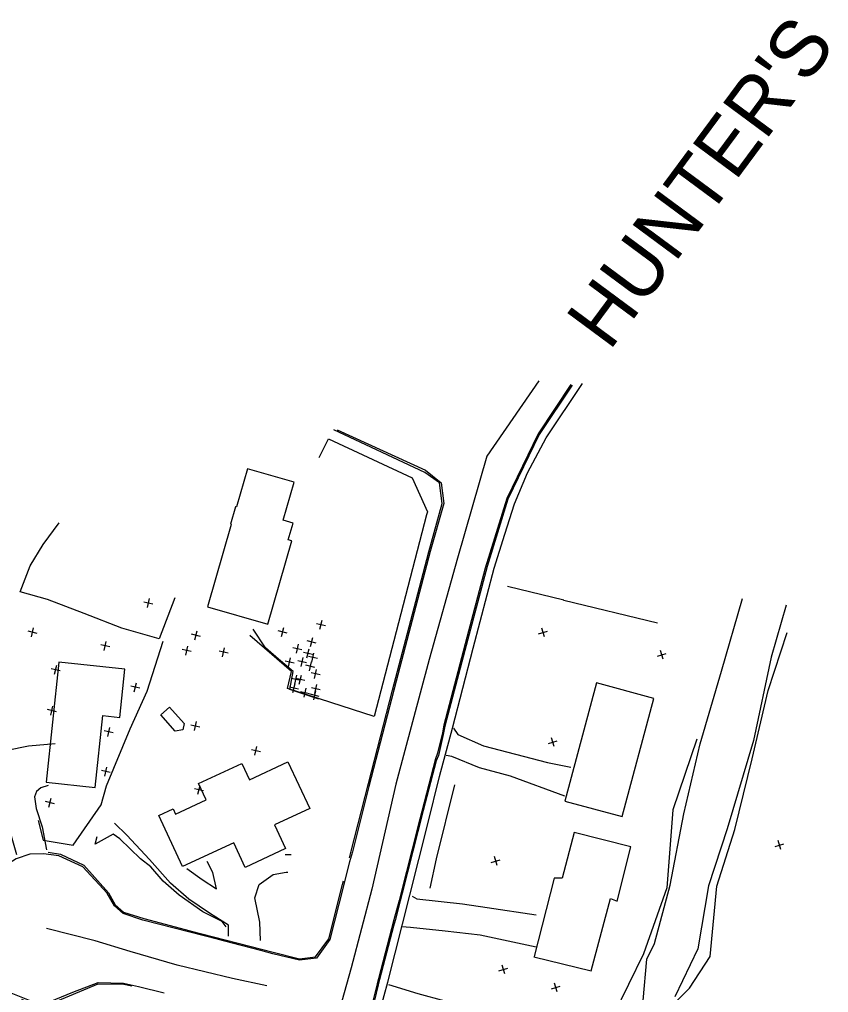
# Model space of a CAD drawing. Extents: x 4711259 to 4716401, y 890074 to 892728.
# Drawn here: x 4713887 to 4714325, y 892014 to 892542 of the extents above; entities that cross this region are included whole.
import ezdxf

# ---------------------------------------------------------------- set-up
doc = ezdxf.new("R2010")
doc.units = 0
for name, color, linetype in [('E_HY_STORM_Ditch', 7, 'Continuous'), ('E_RDWY_PHOTOG_Eave', 7, 'Continuous'), ('E_RDWY_PHOTOG_Fence', 7, 'Continuous'), ('E_RDWY_ROAD_Approach', 7, 'Continuous'), ('E_RDWY_ROAD_Curb', 7, 'Continuous'), ('E_RDWY_ROAD_Fence', 7, 'Continuous'), ('E_RDWY_ROAD_NameTx', 7, 'Continuous'), ('E_RDWY_ROAD_Sidewalk', 7, 'Continuous'), ('E_RDWY_ROAD_TBofCurb', 7, 'Continuous'), ('E_TERR_DTM_BrkLines', 7, 'Continuous'), ('E_TERR_DTM_RandomPt', 7, 'Continuous')]:
    doc.layers.add(name, color=color, linetype=linetype)

msp = doc.modelspace()

# ---------------------------------------------------------------- linework, layer by layer
at = {"layer": 'E_HY_STORM_Ditch'}
for points in [[(4714224.77, 892009.61), (4714226.65, 892032.11), (4714230.83, 892040.51), (4714239.33, 892072.28), (4714246.81, 892110.99), (4714255.61, 892148.9), (4714267.28, 892188.36), (4714278.6, 892227.78)], [(4714302.3, 892224.08), (4714294.17, 892195.83), (4714284.66, 892150.64), (4714270.27, 892102.78), (4714260.1, 892071.81), (4714254.33, 892037.64), (4714241.88, 892011.7)]]:
    msp.add_lwpolyline(points, dxfattribs=at)
at = {"layer": 'E_RDWY_PHOTOG_Eave'}
for points in [[(4714021.22, 892213.8), (4714034.23, 892258.99), (4714032.31, 892259.54), (4714034.91, 892268.56), (4714029.45, 892270.13), (4714035.4, 892290.81), (4714010.19, 892298.06), (4714004.23, 892277.36), (4714003.65, 892277.52), (4714000.92, 892268.02), (4714001.28, 892267.91), (4713988.42, 892223.24)], [(4713927.55, 892125.22), (4713931.66, 892164.16), (4713940.85, 892163.19), (4713943.63, 892189.44), (4713907.94, 892193.21), (4713901.06, 892128.02)], [(4714199.5, 892181.91), (4714182.23, 892117.81), (4714213.33, 892109.43), (4714230.6, 892173.53)], [(4713967.88, 892168.81), (4713975.87, 892159.82), (4713975.11, 892156.42), (4713970.95, 892155.7), (4713963.08, 892164.55)], [(4713983.65, 892127.35), (4714007.07, 892138.26), (4714011.2, 892129.4), (4714032.13, 892139.15), (4714043.94, 892113.78), (4714024.77, 892104.85), (4714030.75, 892092.02), (4714008.95, 892081.87), (4714002.71, 892095.25), (4713974.92, 892082.31), (4713962.03, 892109.99), (4713969.81, 892113.61), (4713971.12, 892110.78), (4713987.75, 892118.53)]]:
    msp.add_lwpolyline(points, close=True, dxfattribs=at)
msp.add_lwpolyline([(4714165.49, 892033.38), (4714196.59, 892025.71), (4714206.95, 892065.06), (4714210.63, 892063.51), (4714218.14, 892092.92), (4714187.26, 892100.83), (4714180.83, 892076), (4714176.44, 892075.94), (4714165.58, 892033.54), (4714165.58, 892033.54)], dxfattribs=at)
at = {"layer": 'E_RDWY_PHOTOG_Fence'}
for points in [[(4714049.02, 892304.21), (4714054.1, 892314.4), (4714099.51, 892293.18), (4714107.77, 892274.68), (4714107.22, 892273.19), (4714090.84, 892209.63), (4714078.92, 892163.65), (4714031.93, 892178.96), (4714034.01, 892188.12), (4714011.51, 892207.65)], [(4714232.46, 892214.26), (4714181.72, 892226.68), (4714181.72, 892226.8), (4714151.09, 892234.28)], [(4713896.64, 892107.28), (4713899.42, 892096.55), (4713915.64, 892093.89), (4713930.79, 892115.78), (4713933.71, 892126.18), (4713946.59, 892156.96), (4713955.76, 892177.52), (4713964.49, 892204.56)]]:
    msp.add_lwpolyline(points, dxfattribs=at)
at = {"layer": 'E_RDWY_ROAD_Approach'}
for points in [[(4714121.86, 892157.45), (4714124.31, 892153.96), (4714138.2, 892147.72), (4714172.95, 892138.83), (4714185.43, 892136.29)], [(4713885.12, 892088.7), (4713881.53, 892101.38), (4713879.59, 892113.76), (4713872.89, 892119.45), (4713866.06, 892130.02), (4713866.28, 892138.39), (4713879.91, 892145.37), (4713891.41, 892147.84), (4713905.89, 892149.14)], [(4714182.26, 892120.45), (4714152.85, 892131.25), (4714135.92, 892135.87), (4714120.97, 892142.03), (4714117.99, 892142.53)], [(4713902.04, 892126.24), (4713898.08, 892125.03), (4713895.79, 892122.95), (4713894.59, 892120.11), (4713895.56, 892113.87), (4713898.9, 892103.94), (4713901.11, 892091.29)], [(4713999.92, 892044.49), (4713999.95, 892050.45), (4713989.61, 892057.05), (4713978.32, 892064.64), (4713968.49, 892073.21), (4713956.95, 892086.18), (4713944.73, 892099.29), (4713938.01, 892105.93)], [(4714033.9, 892088.7), (4714030.63, 892088.64)], [(4713977.24, 892081.28), (4713985.56, 892075.29), (4713993.34, 892070.17), (4713991.37, 892079.03), (4713988.23, 892085.08)], [(4714017.29, 892042.2), (4714016.83, 892052.05), (4714014.1, 892065.33), (4714016.58, 892072.62), (4714024.02, 892078.07), (4714031.16, 892079.24), (4714032.13, 892079.2)], [(4714099.42, 892066.31), (4714101.94, 892064.71), (4714126.77, 892062.03), (4714140.23, 892060.08), (4714166.8, 892056.2)], [(4714166.69, 892038.64), (4714136.36, 892045.02), (4714117.37, 892047.18), (4714098.53, 892049.17), (4714093.91, 892049.62)], [(4714086.66, 892018.41), (4714102.6, 892013.4), (4714131.87, 892005.49), (4714133.24, 892005.31), (4714129.98, 891991.54), (4714101.4, 891997.44), (4714081.87, 891999.61)]]:
    msp.add_lwpolyline(points, dxfattribs=at)
at = {"layer": 'E_RDWY_ROAD_Curb'}
for points in [[(4714185.59, 892343.87), (4714167.83, 892317.05), (4714150.75, 892281.89), (4714139.14, 892244.17), (4714129.12, 892206.5), (4714116.62, 892158.93), (4714115.84, 892154.79), (4714113.27, 892143.75), (4714112.11, 892140.68), (4714102.32, 892103.11), (4714093.52, 892068.32), (4714092.5, 892063.96), (4714089.62, 892053.49), (4714081.27, 892021.32), (4714080.55, 892018.71), (4714076.89, 892004.21)], [(4714058.84, 892319.23), (4714106.63, 892297.27), (4714115.14, 892290.55), (4714116.56, 892279.31), (4714109.3, 892253.16), (4714090.75, 892182.91), (4714075.98, 892125.67), (4714067.07, 892090.34), (4714065.54, 892084.79), (4714063.16, 892075.73), (4714062.25, 892071.91), (4714054.78, 892042.65), (4714047.64, 892032.69), (4714038.41, 892031.48), (4714023.91, 892034.98)], [(4714023.91, 892034.98), (4714017.42, 892036.71), (4714001.97, 892040.77), (4713994.49, 892042.66), (4713970.45, 892048.83), (4713953.32, 892053.28), (4713942.78, 892056.81), (4713938.03, 892060.92), (4713934.02, 892067.79), (4713920.81, 892082.1), (4713907.85, 892088.19), (4713899.49, 892089.29), (4713892.15, 892089.02), (4713884.8, 892086.46), (4713875.68, 892080.9), (4713868.1, 892073.81), (4713864.21, 892068.13), (4713861.6, 892061.34), (4713859.71, 892049.58), (4713860.7, 892038.1), (4713863.41, 892029.26), (4713873.16, 892019.33), (4713880.92, 892014.1), (4713891.71, 892009.84)], [(4713903.21, 892009.01), (4713915.39, 892014.11), (4713929.19, 892019.4), (4713942.9, 892019.01), (4713951.12, 892017.28), (4713964.96, 892013.71)]]:
    msp.add_lwpolyline(points, dxfattribs=at)
at = {"layer": 'E_RDWY_ROAD_Fence'}
for points in [[(4713970.77, 892228), (4713962.2, 892205.88), (4713941.99, 892211.56), (4713921.61, 892219.56), (4713901.71, 892227.16), (4713886.89, 892231.39), (4713892.27, 892245.38), (4713899.35, 892257.06), (4713908.06, 892268.73)], [(4714048.93, 892173.03), (4714033.09, 892178.31), (4714034.99, 892188.09), (4714027.02, 892194.74), (4714019.95, 892200.9), (4714013.23, 892211.06)]]:
    msp.add_lwpolyline(points, dxfattribs=at)
at = {"layer": 'E_RDWY_ROAD_Sidewalk'}
msp.add_lwpolyline([(4714078.41, 891990.71), (4714086.26, 892019.55), (4714098.18, 892066.73), (4714107.89, 892105.42), (4714114.38, 892131.2), (4714121.37, 892157.46), (4714132.5, 892200.86), (4714143.98, 892244.16), (4714149.64, 892262.62), (4714154.94, 892279.03), (4714162.04, 892295.84), (4714172.13, 892314.87), (4714191.76, 892344.31)], dxfattribs=at)
at = {"layer": 'E_RDWY_ROAD_TBofCurb'}
for points in [[(4714186.17, 892343.39), (4714168.35, 892316.66), (4714151.38, 892281.65), (4714140.16, 892245.03), (4714129.58, 892205.72), (4714117.22, 892158.51), (4714116.25, 892153.93), (4714113.8, 892142.54), (4714112.46, 892139.63), (4714105.45, 892112.78), (4714094.05, 892067.92), (4714093, 892063.74), (4714090.17, 892053), (4714089.41, 892049.92), (4714081.83, 892020.96), (4714081.11, 892018.16), (4714077.58, 892003.88)], [(4714065.54, 892087.02), (4714066.47, 892090.69), (4714075.82, 892127.4), (4714088.75, 892177.97), (4714101.44, 892226.15), (4714108.59, 892252.98), (4714115.77, 892279.24), (4714114.23, 892290.4), (4714106.41, 892296.14), (4714057.03, 892319.27)], [(4713902.02, 892090.18), (4713908.68, 892089.08), (4713921.43, 892083), (4713934.72, 892068.11), (4713938.44, 892061.58), (4713942.9, 892057.63), (4713953.93, 892054.05), (4713979.08, 892047.5), (4714024.08, 892035.88)], [(4714024.08, 892035.88), (4714038.36, 892032.23), (4714047.13, 892033.35), (4714054.24, 892043.09), (4714061.78, 892072.48), (4714062.24, 892074.52)], [(4713947.37, 892017.37), (4713943.1, 892018.25), (4713929.03, 892018.49), (4713903.59, 892007.88), (4713890.93, 892008.91), (4713887.83, 892010.1)]]:
    msp.add_lwpolyline(points, dxfattribs=at)
at = {"layer": 'E_TERR_DTM_BrkLines'}
for points in [[(4714168.21, 892345.87), (4714139.93, 892304.85), (4714123.98, 892249.61), (4714108.73, 892194.68), (4714090.62, 892126.91), (4714077.61, 892070.09), (4714066.36, 892027.31), (4714051.14, 891973.2), (4714037.46, 891917.08), (4714024.07, 891859.57), (4714022.9, 891844.03), (4714023.74, 891795.26), (4714028.59, 891737.22), (4714034.45, 891684.14), (4714037.34, 891645.06), (4714038.63, 891626.49), (4714035.43, 891578.63), (4714032.35, 891531.62), (4714024.41, 891465.89), (4714020.79, 891430.37), (4714019.31, 891383.24)], [(4714226.91, 891993.34), (4714249.79, 892016.32), (4714261.05, 892033.57), (4714264.69, 892071.58), (4714274.41, 892102.38), (4714283.88, 892140.78), (4714292.61, 892177.74), (4714302.89, 892209.33)], [(4714253.82, 892151.5), (4714240.84, 892113.08), (4714237.67, 892070.75), (4714224.89, 892034.98), (4714208.58, 892001.73)], [(4714109.29, 892070.67), (4714112.58, 892086.51), (4714122.58, 892126.63)], [(4713998.56, 892049.67), (4713996.5, 892052.5), (4713986, 892057.8), (4713973.06, 892066.86), (4713964.45, 892074.36), (4713957.73, 892082.16), (4713952.08, 892086.42), (4713940.86, 892097.33), (4713937.32, 892099.91), (4713927.53, 892094.52), (4713928.6, 892098.56)], [(4714020.67, 892017.52), (4714002.03, 892021.5), (4713972.09, 892028.76), (4713946.45, 892036.15), (4713927.53, 892042.04), (4713901.1, 892048.63)]]:
    msp.add_lwpolyline(points, dxfattribs=at)
at = {"layer": 'E_TERR_DTM_RandomPt'}
for p, q in [((4713958.91, 892224.68), (4713954.04, 892225.82)), ((4713955.91, 892222.82), (4713957.05, 892227.68)), ((4714052.47, 892212.9), (4714047.6, 892214.04)), ((4714049.46, 892211.03), (4714050.6, 892215.9)), ((4713896.03, 892208.78), (4713891.16, 892209.92)), ((4713893.02, 892206.92), (4713894.16, 892211.79)), ((4713984.66, 892207.18), (4713979.79, 892208.32)), ((4713981.65, 892205.32), (4713982.79, 892210.19)), ((4714031.66, 892208.96), (4714026.79, 892210.1)), ((4714028.65, 892207.1), (4714029.8, 892211.97)), ((4714168.05, 892208.57), (4714172.84, 892210.02)), ((4714171.17, 892206.9), (4714169.72, 892211.69)), ((4713935.47, 892201.46), (4713930.6, 892202.6)), ((4713932.46, 892199.6), (4713933.61, 892204.47)), ((4713976.65, 892197.07), (4713977.8, 892201.93)), ((4714036.68, 892198.02), (4714037.82, 892202.89)), ((4714047.39, 892203.56), (4714042.53, 892204.71)), ((4714044.39, 892201.7), (4714045.53, 892206.57)), ((4713979.66, 892198.93), (4713974.79, 892200.07)), ((4713999.6, 892198.02), (4713994.73, 892199.17)), ((4713996.59, 892196.16), (4713997.74, 892201.03)), ((4714039.69, 892199.88), (4714034.82, 892201.03)), ((4714045.39, 892197.36), (4714040.53, 892198.51)), ((4714042.39, 892195.5), (4714043.53, 892200.37)), ((4714045.06, 892193.26), (4714046.21, 892198.13)), ((4714232.49, 892196.39), (4714237.28, 892197.83)), ((4714235.61, 892194.72), (4714234.16, 892199.5)), ((4713905.55, 892186.61), (4713906.69, 892191.48)), ((4714035.44, 892192.59), (4714030.57, 892193.73)), ((4714032.44, 892190.73), (4714033.58, 892195.6)), ((4714042.25, 892192.74), (4714037.38, 892193.88)), ((4714039.24, 892190.87), (4714040.39, 892195.74)), ((4714046.74, 892190.35), (4714041.87, 892191.49)), ((4714048.07, 892195.12), (4714043.2, 892196.27)), ((4714043.73, 892188.49), (4714044.88, 892193.35)), ((4713908.55, 892188.48), (4713903.69, 892189.62)), ((4714035.85, 892181.33), (4714036.99, 892186.19)), ((4714038.26, 892181.29), (4714039.4, 892186.16)), ((4714049.54, 892186.26), (4714044.68, 892187.41)), ((4714046.54, 892184.4), (4714047.68, 892189.27)), ((4713948.77, 892177.14), (4713949.91, 892182.01)), ((4714038.85, 892183.19), (4714033.98, 892184.33)), ((4714034.81, 892176.71), (4714035.96, 892181.58)), ((4714041.27, 892183.16), (4714036.4, 892184.3)), ((4714046.65, 892176.23), (4714047.8, 892181.1)), ((4713951.78, 892179), (4713946.91, 892180.15)), ((4714037.82, 892178.57), (4714032.95, 892179.71)), ((4714043.85, 892176.03), (4714038.99, 892177.17)), ((4714040.85, 892174.17), (4714041.99, 892179.03)), ((4714049.07, 892174.63), (4714044.21, 892175.78)), ((4714049.66, 892178.09), (4714044.79, 892179.24)), ((4714046.07, 892172.77), (4714047.21, 892177.64)), ((4713906.5, 892166.28), (4713901.64, 892167.42)), ((4713903.5, 892164.41), (4713904.64, 892169.28)), ((4713981.34, 892156.08), (4713982.48, 892160.94)), ((4713937.36, 892154.77), (4713932.5, 892155.91)), ((4713934.36, 892152.91), (4713935.5, 892157.77)), ((4713984.35, 892157.94), (4713979.48, 892159.08)), ((4714173.33, 892149.04), (4714178.12, 892150.49)), ((4714176.45, 892147.37), (4714175, 892152.16)), ((4714017.15, 892144.51), (4714012.28, 892145.65)), ((4714014.14, 892142.65), (4714015.29, 892147.52)), ((4713935.78, 892133.26), (4713930.92, 892134.4)), ((4713932.78, 892131.39), (4713933.92, 892136.26)), ((4713986.29, 892123.35), (4713981.42, 892124.5)), ((4713983.29, 892121.49), (4713984.43, 892126.36)), ((4713905.5, 892116.37), (4713900.64, 892117.51)), ((4713902.5, 892114.51), (4713903.64, 892119.37)), ((4714299.44, 892091.59), (4714298, 892096.38)), ((4714296.33, 892093.26), (4714301.11, 892094.71)), ((4714142.37, 892084.57), (4714147.16, 892086.01)), ((4714145.49, 892082.9), (4714144.04, 892087.68)), ((4714149.65, 892024.03), (4714148.2, 892028.82)), ((4714146.53, 892025.7), (4714151.32, 892027.15)), ((4714174.99, 892015.94), (4714179.78, 892017.39)), ((4714178.11, 892014.27), (4714176.67, 892019.06))]:
    msp.add_line(p, q, dxfattribs=at)

# ---------------------------------------------------------------- texts
at = {"layer": 'E_RDWY_ROAD_NameTx'}
msp.add_text("HUNTER'S", height=30.84, rotation=53.4899, dxfattribs=at).set_placement((4714206.42, 892361.47))

doc.saveas('drawing.dxf')
